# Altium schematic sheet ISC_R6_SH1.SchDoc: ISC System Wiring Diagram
size B; DrawnBy: Filiberto Clara; Engineer: Filiberto Clara; Organization: LIGO Laboratory; Address1: California Institute of Technology; Address2: Massachusetts Institute of Technology; SheetNumber: 22; SheetTotal: 39
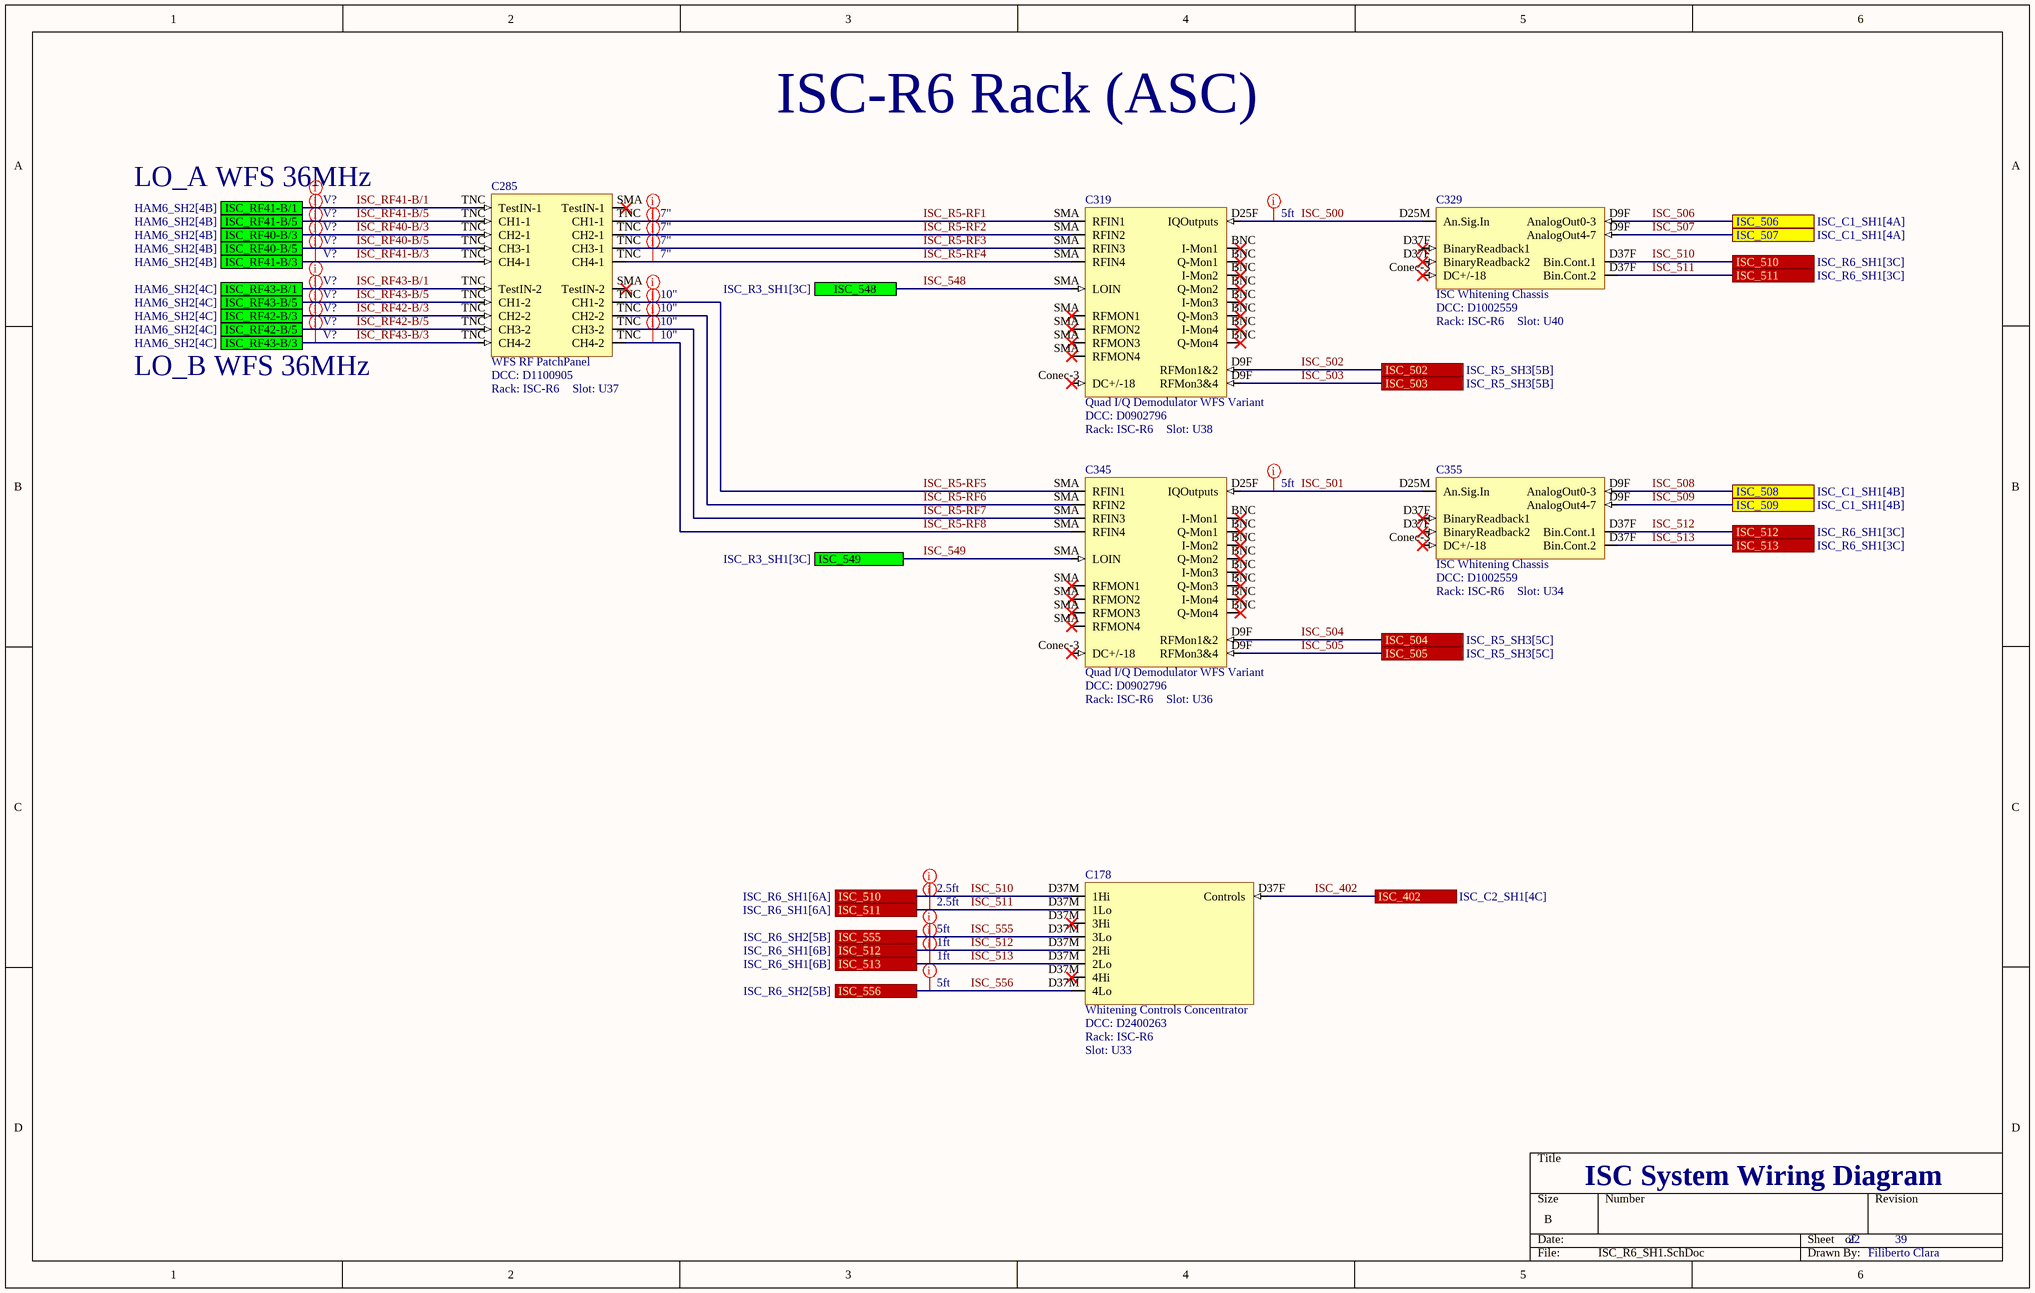
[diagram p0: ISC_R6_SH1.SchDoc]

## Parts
C178  Whitening Controls Concentrator  DCC: D2400263  Rack: ISC-R6  Slot: U33
C285  WFS RF PatchPanel  DCC: D1100905  Rack: ISC-R6  Slot: U37
C319  Quad I/Q Demodulator WFS Variant  DCC: D0902796  Rack: ISC-R6  Slot: U38
C329  ISC Whitening Chassis  DCC: D1002559  Rack: ISC-R6  Slot: U40
C345  Quad I/Q Demodulator WFS Variant  DCC: D0902796  Rack: ISC-R6  Slot: U36
C355  ISC Whitening Chassis  DCC: D1002559  Rack: ISC-R6  Slot: U34

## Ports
ISC_402 (see ISC_C2_SH1[4C]), ISC_502 (see ISC_R5_SH3[5B]), ISC_503 (see ISC_R5_SH3[5B]), ISC_504 (see ISC_R5_SH3[5C]), ISC_505 (see ISC_R5_SH3[5C]), ISC_506 (see ISC_C1_SH1[4A]), ISC_507 (see ISC_C1_SH1[4A]), ISC_508 (see ISC_C1_SH1[4B]), ISC_509 (see ISC_C1_SH1[4B]), ISC_510 (see ISC_R6_SH1[3C]), ISC_510 (see ISC_R6_SH1[6A]), ISC_511 (see ISC_R6_SH1[3C]), ISC_511 (see ISC_R6_SH1[6A]), ISC_512 (see ISC_R6_SH1[3C]), ISC_512 (see ISC_R6_SH1[6B]), ISC_513 (see ISC_R6_SH1[3C]), ISC_513 (see ISC_R6_SH1[6B]), ISC_548 (see ISC_R3_SH1[3C]), ISC_549 (see ISC_R3_SH1[3C]), ISC_555 (see ISC_R6_SH2[5B]), ISC_556 (see ISC_R6_SH2[5B]), ISC_RF40-B/3 (see HAM6_SH2[4B]), ISC_RF40-B/5 (see HAM6_SH2[4B]), ISC_RF41-B/1 (see HAM6_SH2[4B]), ISC_RF41-B/3 (see HAM6_SH2[4B]), ISC_RF41-B/5 (see HAM6_SH2[4B]), ISC_RF42-B/3 (see HAM6_SH2[4C]), ISC_RF42-B/5 (see HAM6_SH2[4C]), ISC_RF43-B/1 (see HAM6_SH2[4C]), ISC_RF43-B/3 (see HAM6_SH2[4C]), ISC_RF43-B/5 (see HAM6_SH2[4C])

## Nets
ISC_402: C178.D37F(Controls) ; port ISC_402
ISC_500: C319.D25F(IQOutputs) C329.D25M(An.Sig.In)
ISC_501: C345.D25F(IQOutputs) C355.D25M(An.Sig.In)
ISC_502: C319.D9F(RFMon1&2) ; port ISC_502
ISC_503: C319.D9F(RFMon3&4) ; port ISC_503
ISC_504: C345.D9F(RFMon1&2) ; port ISC_504
ISC_505: C345.D9F(RFMon3&4) ; port ISC_505
ISC_506: C329.D9F(AnalogOut0-3) ; port ISC_506
ISC_507: C329.D9F(AnalogOut4-7) ; port ISC_507
ISC_508: C355.D9F(AnalogOut0-3) ; port ISC_508
ISC_509: C355.D9F(AnalogOut4-7) ; port ISC_509
ISC_510: C178.D37M(1Hi) C329.D37F(BinaryReadback1) ; port ISC_510
ISC_511: C178.D37M(1Lo) C329.D37F(Bin.Cont.2) ; port ISC_511
ISC_512: C178.D37M(2Hi) C355.D37F(BinaryReadback1) ; port ISC_512
ISC_513: C178.D37M(2Lo) C355.D37F(Bin.Cont.2) ; port ISC_513
ISC_548: C319.SMA(LOIN) ; port ISC_548
ISC_549: C345.SMA(LOIN) ; port ISC_549
ISC_555: C178.D37M(3Lo) ; port ISC_555
ISC_556: C178.D37M(4Lo) ; port ISC_556
ISC_R5-RF1: C285.TNC(CH1-1) C319.SMA(RFIN1)
ISC_R5-RF2: C285.TNC(CH2-1) C319.SMA(RFIN2)
ISC_R5-RF3: C285.TNC(CH3-1) C319.SMA(RFIN3)
ISC_R5-RF4: C285.TNC(CH4-1) C319.SMA(RFIN4)
ISC_R5-RF5: C285.TNC(CH1-2) C345.SMA(RFIN1)
ISC_R5-RF6: C285.TNC(CH2-2) C345.SMA(RFIN2)
ISC_R5-RF7: C285.TNC(CH3-2) C345.SMA(RFIN3)
ISC_R5-RF8: C285.TNC(CH4-2) C345.SMA(RFIN4)
ISC_RF40-B/3: C285.TNC(CH2-1) ; port ISC_RF40-B/3
ISC_RF40-B/5: C285.TNC(CH3-1) ; port ISC_RF40-B/5
ISC_RF41-B/1: C285.TNC(TestIN-1) ; port ISC_RF41-B/1
ISC_RF41-B/3: C285.TNC(CH4-1) ; port ISC_RF41-B/3
ISC_RF41-B/5: C285.TNC(CH1-1) ; port ISC_RF41-B/5
ISC_RF42-B/3: C285.TNC(CH2-2) ; port ISC_RF42-B/3
ISC_RF42-B/5: C285.TNC(CH3-2) ; port ISC_RF42-B/5
ISC_RF43-B/1: C285.TNC(TestIN-2) ; port ISC_RF43-B/1
ISC_RF43-B/3: C285.TNC(CH4-2) ; port ISC_RF43-B/3
ISC_RF43-B/5: C285.TNC(CH1-2) ; port ISC_RF43-B/5

Not connected (* = marked no-connect by the designer): C285 SMA(TestIN-1)*; C319 BNC(I-Mon1)* Conec-3(DC+/-18)*; C329 Conec-3(DC+/-18)*; C345 BNC(I-Mon1)* Conec-3(DC+/-18)*; C355 Conec-3(DC+/-18)*

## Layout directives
Length: 10": ISC_R5-RF5, ISC_R5-RF6, ISC_R5-RF7, ISC_R5-RF8
Length: V?: ISC_RF40-B/3, ISC_RF40-B/5, ISC_RF41-B/1, ISC_RF41-B/3, ISC_RF41-B/5, ISC_RF42-B/3, ISC_RF42-B/5, ISC_RF43-B/1, ISC_RF43-B/3, ISC_RF43-B/5
Length: 5ft: ISC_500, ISC_501, ISC_555, ISC_556
Length: 7": ISC_R5-RF1, ISC_R5-RF2, ISC_R5-RF3, ISC_R5-RF4
Length: 2.5ft: ISC_510, ISC_511
Length: 1ft: ISC_512, ISC_513

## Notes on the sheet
- ISC-R6 Rack (ASC)
- LO_A WFS 36MHz
- LO_B WFS 36MHz

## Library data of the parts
C178 = Whitening Controls Concentrator: Serial: Sxxxxxxx; System: ISC
C285 = WFS RFPD PatchPanel: Serial: Sxxxxxxx; System: ISC
C319 C345 = QuadIQdemod_WFS: Serial: Sxxxxxxx; System: ISC
C329 C355 = ISC Whitening: Serial: Sxxxxxxx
